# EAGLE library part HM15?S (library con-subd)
SUB-D
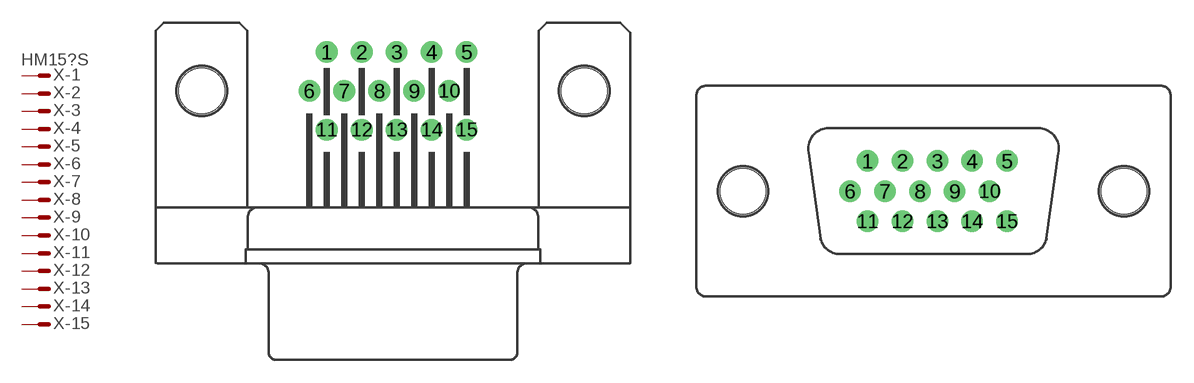
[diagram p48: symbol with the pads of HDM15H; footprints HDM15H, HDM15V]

Designator prefix X; gates -2=M -3=M -4=M -5=M -6=M -7=M -8=M -9=M -10=M -11=M -12=M -13=M -14=M -15=M -1=MV

## HM15HS (OC_FARNELL: unknown; OC_NEWARK: unknown)  [HDM15H]
1  -1:M  pas
2  -2:M  pas
3  -3:M  pas
4  -4:M  pas
5  -5:M  pas
6  -6:M  pas
7  -7:M  pas
8  -8:M  pas
9  -9:M  pas
10  -10:M  pas
11  -11:M  pas
12  -12:M  pas
13  -13:M  pas
14  -14:M  pas
15  -15:M  pas

## HM15VS (OC_FARNELL: unknown; OC_NEWARK: unknown)  [HDM15V]
Pads as for HDM15H

## Footprint HDM15H (pad centres in mm)
SUB-D
drill 0.9 round: 1 -4.329,2.54; 2 -2.043,2.54; 3 0.243,2.54; 4 2.529,2.54; 5 4.815,2.54; 6 -5.472,0; 7 -3.186,0; 8 -0.9,0; 9 1.386,0; 10 3.672,0; 11 -4.329,-2.54; 12 -2.043,-2.54; 13 0.243,-2.54; 14 2.529,-2.54; 15 4.815,-2.54
hole 3 at -12.5,0
hole 3 at 12.5,0

## Footprint HDM15V (pad centres in mm)
SUB-D
drill 0.9 round: 1 -4.324,1.98; 2 -2.038,1.98; 3 0.248,1.98; 4 2.534,1.98; 5 4.82,1.98; 6 -5.467,0; 7 -3.181,0; 8 -0.895,0; 9 1.391,0; 10 3.677,0; 11 -4.324,-1.98; 12 -2.038,-1.98; 13 0.248,-1.98; 14 2.534,-1.98; 15 4.82,-1.98
hole 3 at -12.5,0
hole 3 at 12.5,0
